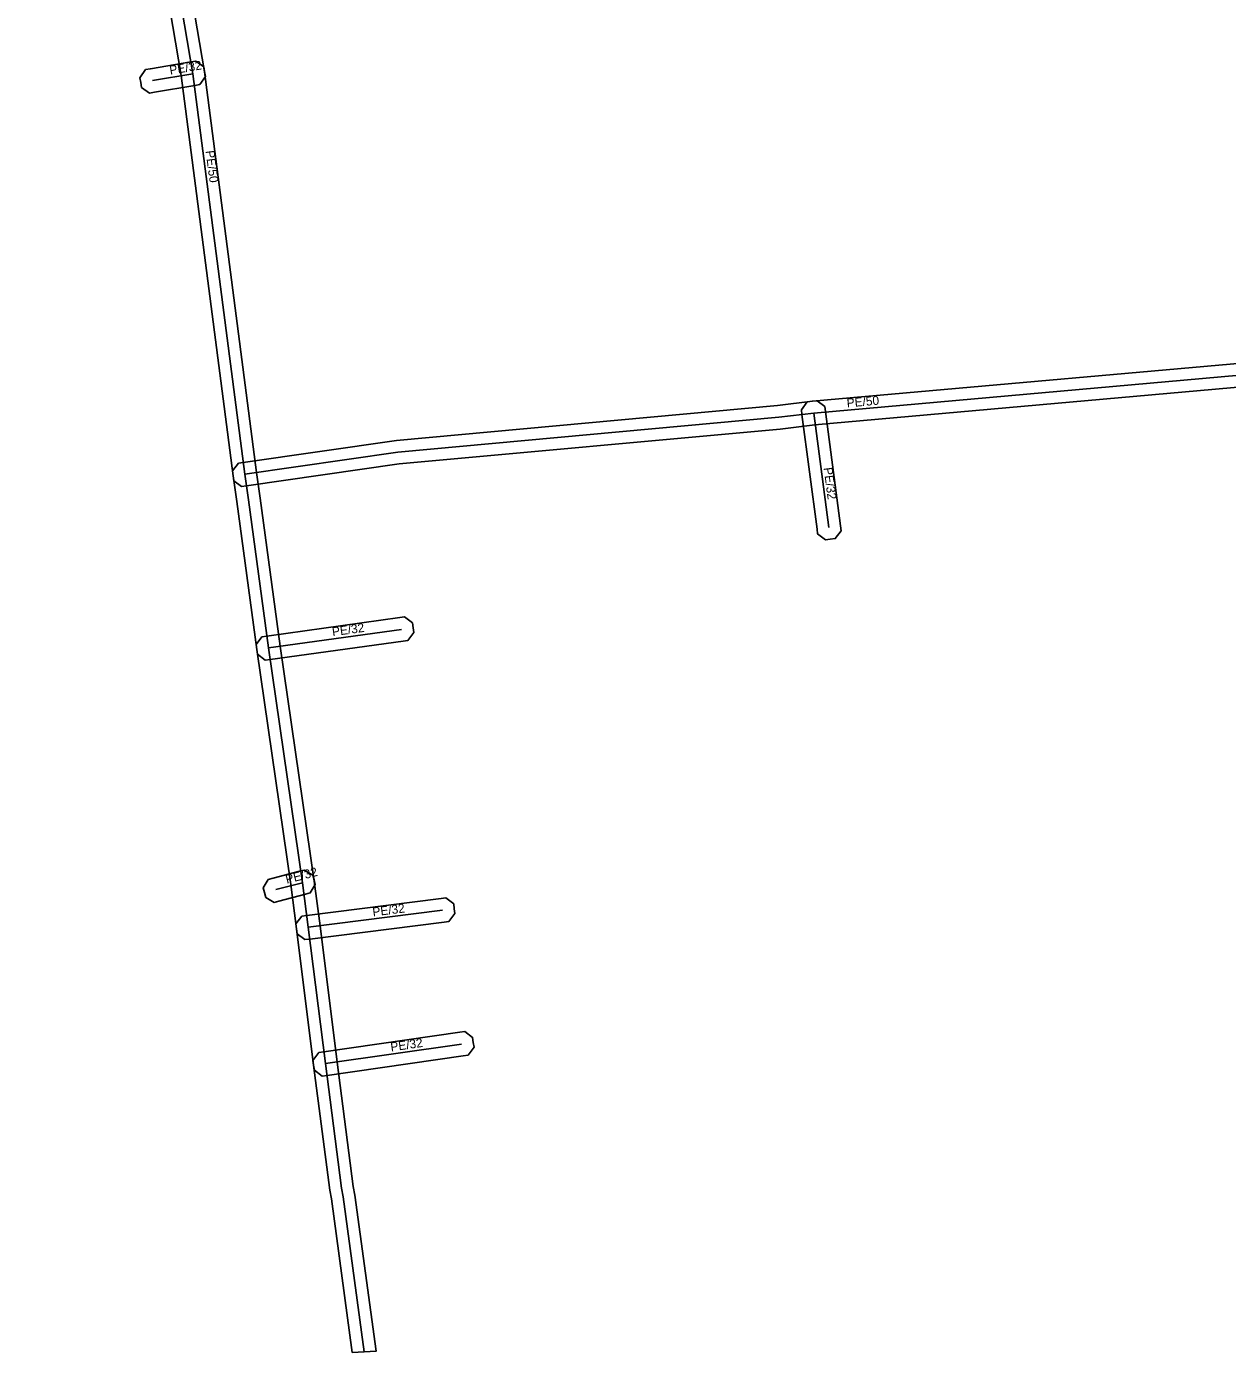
# Model space of a CAD drawing. Extents: x -710999 to -710778, y -1036229 to -1036005.
# Drawn here: x -710998.2 to -710897.1, y -1036228.7 to -1036117 of the extents above; entities that cross this region are included whole.
import ezdxf

# ---------------------------------------------------------------- set-up
doc = ezdxf.new("R2010")
doc.units = 0
for name, color, linetype in [('1', 7, 'Continuous'), ('24', 7, 'Continuous'), ('30', 7, 'Continuous')]:
    doc.layers.add(name, color=color, linetype=linetype)

msp = doc.modelspace()

# ---------------------------------------------------------------- linework, layer by layer
at = {"layer": '1'}
msp.add_lwpolyline([(-710984.85, -1036111.06), (-710983.2, -1036120.82), (-710978.82, -1036154.57), (-710978.52, -1036156.71), (-710976.83, -1036169.18), (-710973.97, -1036188.97), (-710973.48, -1036192.73), (-710972.04, -1036204.21), (-710970.69, -1036214.68), (-710970.55, -1036215.41), (-710968.77, -1036228.56), (-710970.77, -1036228.67), (-710972.53, -1036215.73), (-710972.67, -1036215), (-710974.02, -1036204.47), (-710975.46, -1036192.99), (-710975.95, -1036189.25), (-710978.81, -1036169.46), (-710980.5, -1036156.99), (-710980.8, -1036154.83), (-710985.18, -1036121.12), (-710986.83, -1036111.36)], dxfattribs=at)
for points in [[(-710988.17, -1036120.63), (-710987.76, -1036120.56), (-710984.36, -1036119.98), (-710983.95, -1036119.91), (-710983.27, -1036120.39), (-710983.2, -1036120.8), (-710983.13, -1036121.21), (-710983.61, -1036121.89), (-710984.02, -1036121.96), (-710987.42, -1036122.54), (-710987.83, -1036122.61), (-710988.51, -1036122.13), (-710988.58, -1036121.72), (-710988.65, -1036121.31)], [(-710980.36, -1036153.77), (-710979.95, -1036153.71), (-710967.05, -1036151.86), (-710934.97, -1036148.92), (-710932.04, -1036148.56), (-710888.97, -1036144.73), (-710878.51, -1036142.26), (-710878.11, -1036142.16), (-710877.4, -1036142.6), (-710877.31, -1036143), (-710877.21, -1036143.4), (-710877.65, -1036144.11), (-710878.05, -1036144.2), (-710888.65, -1036146.71), (-710931.83, -1036150.55), (-710934.75, -1036150.9), (-710966.81, -1036153.84), (-710979.67, -1036155.69), (-710980.08, -1036155.75), (-710980.74, -1036155.25), (-710980.8, -1036154.84), (-710980.86, -1036154.43)], [(-710930.99, -1036149.01), (-710930.94, -1036149.42), (-710929.67, -1036159.06), (-710929.61, -1036159.47), (-710930.12, -1036160.13), (-710930.53, -1036160.18), (-710930.94, -1036160.23), (-710931.6, -1036159.73), (-710931.65, -1036159.32), (-710932.92, -1036149.68), (-710932.97, -1036149.27), (-710932.47, -1036148.61), (-710932.06, -1036148.56), (-710931.65, -1036148.51)], [(-710978.37, -1036168.39), (-710977.96, -1036168.33), (-710966.77, -1036166.78), (-710966.36, -1036166.72), (-710965.7, -1036167.22), (-710965.64, -1036167.63), (-710965.58, -1036168.04), (-710966.08, -1036168.7), (-710966.49, -1036168.76), (-710977.68, -1036170.31), (-710978.09, -1036170.37), (-710978.75, -1036169.87), (-710978.81, -1036169.46), (-710978.87, -1036169.05)], [(-710977.84, -1036188.83), (-710977.44, -1036188.72), (-710975.21, -1036188.14), (-710974.81, -1036188.04), (-710974.1, -1036188.46), (-710973.99, -1036188.86), (-710973.89, -1036189.26), (-710974.31, -1036189.97), (-710974.71, -1036190.08), (-710976.94, -1036190.66), (-710977.34, -1036190.76), (-710978.05, -1036190.34), (-710978.16, -1036189.94), (-710978.26, -1036189.54)], [(-710975.01, -1036191.92), (-710974.6, -1036191.87), (-710963.3, -1036190.44), (-710962.89, -1036190.39), (-710962.23, -1036190.89), (-710962.18, -1036191.3), (-710962.13, -1036191.71), (-710962.63, -1036192.37), (-710963.04, -1036192.42), (-710974.34, -1036193.85), (-710974.76, -1036193.9), (-710975.41, -1036193.4), (-710975.46, -1036192.99), (-710975.51, -1036192.58)], [(-710973.58, -1036203.41), (-710973.17, -1036203.35), (-710961.71, -1036201.7), (-710961.3, -1036201.64), (-710960.64, -1036202.14), (-710960.58, -1036202.55), (-710960.52, -1036202.96), (-710961.02, -1036203.62), (-710961.43, -1036203.68), (-710972.89, -1036205.33), (-710973.3, -1036205.39), (-710973.96, -1036204.89), (-710974.02, -1036204.48), (-710974.08, -1036204.07)]]:
    msp.add_lwpolyline(points, close=True, dxfattribs=at)
at = {"layer": '24'}
for points in [[(-710998.19, -1036026.82), (-710997.3, -1036032.3), (-710990.16, -1036081.01), (-710985.84, -1036111.21), (-710984.19, -1036120.97), (-710979.81, -1036154.7), (-710979.51, -1036156.85), (-710977.82, -1036169.32), (-710974.96, -1036189.11), (-710974.47, -1036192.86), (-710973.03, -1036204.34), (-710971.68, -1036214.84), (-710971.54, -1036215.57), (-710969.77, -1036228.62)], [(-710987.59, -1036121.55), (-710984.19, -1036120.97)], [(-710979.81, -1036154.7), (-710966.93, -1036152.85), (-710934.86, -1036149.91), (-710931.93, -1036149.55), (-710888.81, -1036145.72), (-710878.28, -1036143.23)], [(-710931.93, -1036149.55), (-710930.66, -1036159.19)], [(-710977.82, -1036169.32), (-710966.63, -1036167.77)], [(-710977.19, -1036189.69), (-710974.96, -1036189.11)], [(-710974.47, -1036192.86), (-710963.17, -1036191.43)], [(-710973.03, -1036204.34), (-710961.57, -1036202.69)]]:
    msp.add_lwpolyline(points, dxfattribs=at)

# ---------------------------------------------------------------- texts
at = {"layer": '30'}
for s, rotation, p in [('PE/32', 9.6808, (-710986.09, -1036121.06)), ('PE/50', 277.3987, (-710983.12, -1036127.48)), ('PE/50', 5.0758, (-710929.12, -1036149.08)), ('PE/32', 277.5051, (-710931.1, -1036154.17)), ('PE/32', 7.8862, (-710972.42, -1036168.35)), ('PE/32', 14.579, (-710976.28, -1036189.2)), ('PE/32', 7.2124, (-710969.02, -1036191.95)), ('PE/32', 8.1931, (-710967.5, -1036203.32))]:
    msp.add_text(s, height=0.75, rotation=rotation, dxfattribs=at).set_placement(p)

doc.saveas('drawing.dxf')
